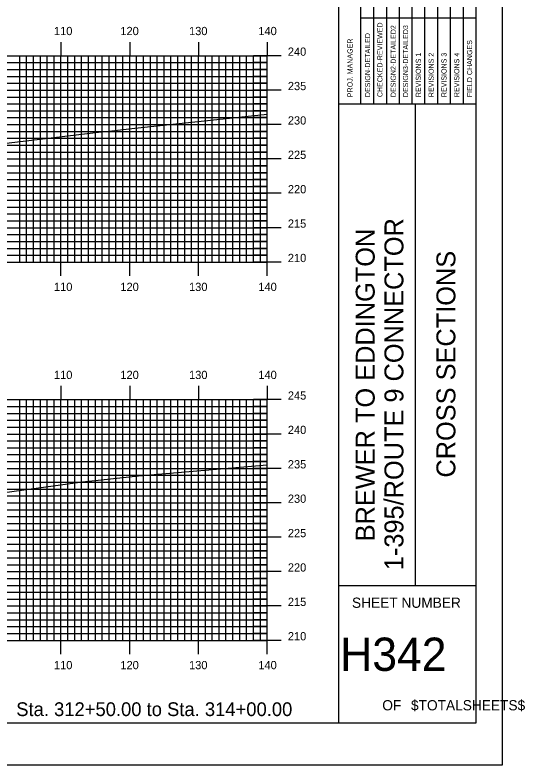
# Model space of a CAD drawing. Extents: x 1818850 to 1819194, y 442591 to 442811.
# Drawn here: x 1819119.5 to 1819193.6, y 442590.5 to 442699.6 of the extents above; entities that cross this region are included whole.
import ezdxf

# ---------------------------------------------------------------- set-up
doc = ezdxf.new("R2010")
doc.units = 0
for name, color, linetype in [('BORDER', 7, 'Continuous'), ('H_V ANNOTATION', 7, 'Continuous'), ('MAJOR', 7, 'Continuous'), ('MINOR', 7, 'Continuous'), ('PLOT BOUNDARY', 7, 'Continuous'), ('S_Roadway_Centerline', 7, 'Continuous')]:
    doc.layers.add(name, color=color, linetype=linetype)

msp = doc.modelspace()

# ---------------------------------------------------------------- linework, layer by layer
at = {"layer": 'BORDER'}
for p, q in [((1819166.55, 442596.67), (1819166.55, 442806.67)), ((1819166.55, 442686.67), (1819186.55, 442686.67)), ((1819177.73, 442616.67), (1819177.73, 442686.67)), ((1819166.55, 442616.67), (1819186.55, 442616.67))]:
    msp.add_line(p, q, dxfattribs=at)
msp.add_lwpolyline([(1818866.55, 442596.67), (1819186.55, 442596.67), (1819186.55, 442806.67), (1818866.55, 442806.67)], close=True, dxfattribs=at)
for points in [[(1819171.65, 442686.68), (1819171.65, 442721.67)], [(1819173.51, 442721.67), (1819173.51, 442686.68)], [(1819175.37, 442686.68), (1819175.37, 442721.67)], [(1819177.24, 442686.68), (1819177.24, 442721.67)], [(1819179.1, 442686.68), (1819179.1, 442721.67)], [(1819180.96, 442686.68), (1819180.96, 442721.67)], [(1819182.83, 442686.68), (1819182.83, 442721.67)], [(1819184.69, 442686.68), (1819184.69, 442721.67)], [(1819169.78, 442686.68), (1819169.78, 442720.26)], [(1819169.78, 442699.17), (1819186.55, 442699.17)]]:
    msp.add_lwpolyline(points, dxfattribs=at)
at = {"layer": 'MAJOR'}
for p, q in [((1819126.15, 442695.67), (1819126.15, 442693.67)), ((1819136.15, 442695.67), (1819136.15, 442693.67)), ((1819146.15, 442695.67), (1819146.15, 442693.67)), ((1819156.15, 442695.67), (1819156.15, 442693.67)), ((1818876.15, 442693.67), (1819156.15, 442693.67)), ((1818876.15, 442693.67), (1819156.15, 442693.67)), ((1819126.15, 442663.67), (1819126.15, 442693.67)), ((1819136.15, 442663.67), (1819136.15, 442693.67)), ((1819146.15, 442663.67), (1819146.15, 442693.67)), ((1819158.16, 442693.67), (1819154.15, 442693.67)), ((1819156.15, 442663.67), (1819156.15, 442693.67)), ((1819156.15, 442663.67), (1819156.15, 442693.67)), ((1818876.15, 442688.67), (1819156.15, 442688.67)), ((1819158.16, 442688.67), (1819154.15, 442688.67)), ((1818876.15, 442683.67), (1819156.15, 442683.67)), ((1819158.16, 442683.67), (1819154.15, 442683.67)), ((1818876.15, 442678.67), (1819156.15, 442678.67)), ((1819158.16, 442678.67), (1819154.15, 442678.67)), ((1818876.15, 442673.67), (1819156.15, 442673.67)), ((1819158.16, 442673.67), (1819154.15, 442673.67)), ((1818876.15, 442668.67), (1819156.15, 442668.67)), ((1819158.16, 442668.67), (1819154.15, 442668.67)), ((1818876.15, 442663.67), (1819156.15, 442663.67)), ((1818876.15, 442663.67), (1819156.15, 442663.67)), ((1819126.15, 442661.66), (1819126.15, 442663.67)), ((1819136.15, 442661.66), (1819136.15, 442663.67)), ((1819146.15, 442661.66), (1819146.15, 442663.67)), ((1819158.16, 442663.67), (1819154.15, 442663.67)), ((1819156.15, 442661.66), (1819156.15, 442663.67)), ((1819126.15, 442645.67), (1819126.15, 442643.67)), ((1819136.15, 442645.67), (1819136.15, 442643.67)), ((1819146.15, 442645.67), (1819146.15, 442643.67)), ((1819156.15, 442645.67), (1819156.15, 442643.67)), ((1818876.15, 442643.67), (1819156.15, 442643.67)), ((1818876.15, 442643.67), (1819156.15, 442643.67)), ((1819126.15, 442608.67), (1819126.15, 442643.67)), ((1819136.15, 442608.67), (1819136.15, 442643.67)), ((1819146.15, 442608.67), (1819146.15, 442643.67)), ((1819158.16, 442643.67), (1819154.15, 442643.67)), ((1819156.15, 442608.67), (1819156.15, 442643.67)), ((1819156.15, 442608.67), (1819156.15, 442643.67)), ((1818876.15, 442638.67), (1819156.15, 442638.67)), ((1819158.16, 442638.67), (1819154.15, 442638.67)), ((1818876.15, 442633.67), (1819156.15, 442633.67)), ((1819158.16, 442633.67), (1819154.15, 442633.67)), ((1818876.15, 442628.67), (1819156.15, 442628.67)), ((1819158.16, 442628.67), (1819154.15, 442628.67)), ((1818876.15, 442623.67), (1819156.15, 442623.67)), ((1819158.16, 442623.67), (1819154.15, 442623.67)), ((1818876.15, 442618.67), (1819156.15, 442618.67)), ((1819158.16, 442618.67), (1819154.15, 442618.67)), ((1818876.15, 442613.67), (1819156.15, 442613.67)), ((1819158.16, 442613.67), (1819154.15, 442613.67)), ((1818876.15, 442608.67), (1819156.15, 442608.67)), ((1818876.15, 442608.67), (1819156.15, 442608.67)), ((1819126.15, 442606.66), (1819126.15, 442608.67)), ((1819136.15, 442606.66), (1819136.15, 442608.67)), ((1819146.15, 442606.66), (1819146.15, 442608.67)), ((1819158.16, 442608.67), (1819154.15, 442608.67)), ((1819156.15, 442606.66), (1819156.15, 442608.67))]:
    msp.add_line(p, q, dxfattribs=at)
at = {"layer": 'MINOR'}
for p, q in [((1819120.15, 442663.67), (1819120.15, 442693.67)), ((1819121.15, 442663.67), (1819121.15, 442693.67)), ((1819122.15, 442663.67), (1819122.15, 442693.67)), ((1819123.15, 442663.67), (1819123.15, 442693.67)), ((1819124.15, 442663.67), (1819124.15, 442693.67)), ((1819125.15, 442663.67), (1819125.15, 442693.67)), ((1819127.15, 442663.67), (1819127.15, 442693.67)), ((1819128.15, 442663.67), (1819128.15, 442693.67)), ((1819129.15, 442663.67), (1819129.15, 442693.67)), ((1819130.15, 442663.67), (1819130.15, 442693.67)), ((1819131.15, 442663.67), (1819131.15, 442693.67)), ((1819132.15, 442663.67), (1819132.15, 442693.67)), ((1819133.15, 442663.67), (1819133.15, 442693.67)), ((1819134.15, 442663.67), (1819134.15, 442693.67)), ((1819135.15, 442663.67), (1819135.15, 442693.67)), ((1819137.15, 442663.67), (1819137.15, 442693.67)), ((1819138.15, 442663.67), (1819138.15, 442693.67)), ((1819139.15, 442663.67), (1819139.15, 442693.67)), ((1819140.15, 442663.67), (1819140.15, 442693.67)), ((1819141.15, 442663.67), (1819141.15, 442693.67)), ((1819142.15, 442663.67), (1819142.15, 442693.67)), ((1819143.15, 442663.67), (1819143.15, 442693.67)), ((1819144.15, 442663.67), (1819144.15, 442693.67)), ((1819145.15, 442663.67), (1819145.15, 442693.67)), ((1819147.15, 442663.67), (1819147.15, 442693.67)), ((1819148.15, 442663.67), (1819148.15, 442693.67)), ((1819149.15, 442663.67), (1819149.15, 442693.67)), ((1819150.15, 442663.67), (1819150.15, 442693.67)), ((1819151.15, 442663.67), (1819151.15, 442693.67)), ((1819152.15, 442663.67), (1819152.15, 442693.67)), ((1819153.15, 442663.67), (1819153.15, 442693.67)), ((1819154.15, 442663.67), (1819154.15, 442693.67)), ((1819155.15, 442663.67), (1819155.15, 442693.67)), ((1818876.15, 442692.67), (1819156.15, 442692.67)), ((1818876.15, 442691.67), (1819156.15, 442691.67)), ((1819156.15, 442692.67), (1819154.15, 442692.67)), ((1819156.15, 442691.67), (1819154.15, 442691.67)), ((1818876.15, 442690.67), (1819156.15, 442690.67)), ((1819156.15, 442690.67), (1819154.15, 442690.67)), ((1818876.15, 442689.67), (1819156.15, 442689.67)), ((1819156.15, 442689.67), (1819154.15, 442689.67)), ((1818876.15, 442687.67), (1819156.15, 442687.67)), ((1819156.15, 442687.67), (1819154.15, 442687.67)), ((1818876.15, 442686.67), (1819156.15, 442686.67)), ((1819156.15, 442686.67), (1819154.15, 442686.67)), ((1818876.15, 442685.67), (1819156.15, 442685.67)), ((1819156.15, 442685.67), (1819154.15, 442685.67)), ((1818876.15, 442684.67), (1819156.15, 442684.67)), ((1819156.15, 442684.67), (1819154.15, 442684.67)), ((1818876.15, 442682.67), (1819156.15, 442682.67)), ((1819156.15, 442682.67), (1819154.15, 442682.67)), ((1818876.15, 442681.67), (1819156.15, 442681.67)), ((1819156.15, 442681.67), (1819154.15, 442681.67)), ((1818876.15, 442680.67), (1819156.15, 442680.67)), ((1818876.15, 442679.67), (1819156.15, 442679.67)), ((1819156.15, 442680.67), (1819154.15, 442680.67)), ((1819156.15, 442679.67), (1819154.15, 442679.67)), ((1818876.15, 442677.67), (1819156.15, 442677.67)), ((1819156.15, 442677.67), (1819154.15, 442677.67)), ((1818876.15, 442676.67), (1819156.15, 442676.67)), ((1819156.15, 442676.67), (1819154.15, 442676.67)), ((1818876.15, 442675.67), (1819156.15, 442675.67)), ((1819156.15, 442675.67), (1819154.15, 442675.67)), ((1818876.15, 442674.67), (1819156.15, 442674.67)), ((1819156.15, 442674.67), (1819154.15, 442674.67)), ((1818876.15, 442672.67), (1819156.15, 442672.67)), ((1819156.15, 442672.67), (1819154.15, 442672.67)), ((1818876.15, 442671.67), (1819156.15, 442671.67)), ((1819156.15, 442671.67), (1819154.15, 442671.67)), ((1818876.15, 442670.67), (1819156.15, 442670.67)), ((1819156.15, 442670.67), (1819154.15, 442670.67)), ((1818876.15, 442669.67), (1819156.15, 442669.67)), ((1819156.15, 442669.67), (1819154.15, 442669.67)), ((1818876.15, 442667.67), (1819156.15, 442667.67)), ((1819156.15, 442667.67), (1819154.15, 442667.67)), ((1818876.15, 442666.67), (1819156.15, 442666.67)), ((1819156.15, 442666.67), (1819154.15, 442666.67)), ((1818876.15, 442665.67), (1819156.15, 442665.67)), ((1819156.15, 442665.67), (1819154.15, 442665.67)), ((1818876.15, 442664.67), (1819156.15, 442664.67)), ((1819156.15, 442664.67), (1819154.15, 442664.67)), ((1819120.15, 442608.67), (1819120.15, 442643.67)), ((1819121.15, 442608.67), (1819121.15, 442643.67)), ((1819122.15, 442608.67), (1819122.15, 442643.67)), ((1819123.15, 442608.67), (1819123.15, 442643.67)), ((1819124.15, 442608.67), (1819124.15, 442643.67)), ((1819125.15, 442608.67), (1819125.15, 442643.67)), ((1819127.15, 442608.67), (1819127.15, 442643.67)), ((1819128.15, 442608.67), (1819128.15, 442643.67)), ((1819129.15, 442608.67), (1819129.15, 442643.67)), ((1819130.15, 442608.67), (1819130.15, 442643.67)), ((1819131.15, 442608.67), (1819131.15, 442643.67)), ((1819132.15, 442608.67), (1819132.15, 442643.67)), ((1819133.15, 442608.67), (1819133.15, 442643.67)), ((1819134.15, 442608.67), (1819134.15, 442643.67)), ((1819135.15, 442608.67), (1819135.15, 442643.67)), ((1819137.15, 442608.67), (1819137.15, 442643.67)), ((1819138.15, 442608.67), (1819138.15, 442643.67)), ((1819139.15, 442608.67), (1819139.15, 442643.67)), ((1819140.15, 442608.67), (1819140.15, 442643.67)), ((1819141.15, 442608.67), (1819141.15, 442643.67)), ((1819142.15, 442608.67), (1819142.15, 442643.67)), ((1819143.15, 442608.67), (1819143.15, 442643.67)), ((1819144.15, 442608.67), (1819144.15, 442643.67)), ((1819145.15, 442608.67), (1819145.15, 442643.67)), ((1819147.15, 442608.67), (1819147.15, 442643.67)), ((1819148.15, 442608.67), (1819148.15, 442643.67)), ((1819149.15, 442608.67), (1819149.15, 442643.67)), ((1819150.15, 442608.67), (1819150.15, 442643.67)), ((1819151.15, 442608.67), (1819151.15, 442643.67)), ((1819152.15, 442608.67), (1819152.15, 442643.67)), ((1819153.15, 442608.67), (1819153.15, 442643.67)), ((1819154.15, 442608.67), (1819154.15, 442643.67)), ((1819155.15, 442608.67), (1819155.15, 442643.67)), ((1818876.15, 442642.67), (1819156.15, 442642.67)), ((1819156.15, 442642.67), (1819154.15, 442642.67)), ((1818876.15, 442641.67), (1819156.15, 442641.67)), ((1819156.15, 442641.67), (1819154.15, 442641.67)), ((1818876.15, 442640.67), (1819156.15, 442640.67)), ((1819156.15, 442640.67), (1819154.15, 442640.67)), ((1818876.15, 442639.67), (1819156.15, 442639.67)), ((1819156.15, 442639.67), (1819154.15, 442639.67)), ((1818876.15, 442637.67), (1819156.15, 442637.67)), ((1819156.15, 442637.67), (1819154.15, 442637.67)), ((1818876.15, 442636.67), (1819156.15, 442636.67)), ((1819156.15, 442636.67), (1819154.15, 442636.67)), ((1818876.15, 442635.67), (1819156.15, 442635.67)), ((1819156.15, 442635.67), (1819154.15, 442635.67)), ((1818876.15, 442634.67), (1819156.15, 442634.67)), ((1819156.15, 442634.67), (1819154.15, 442634.67)), ((1818876.15, 442632.67), (1819156.15, 442632.67)), ((1819156.15, 442632.67), (1819154.15, 442632.67)), ((1818876.15, 442631.67), (1819156.15, 442631.67)), ((1818876.15, 442630.67), (1819156.15, 442630.67)), ((1819156.15, 442631.67), (1819154.15, 442631.67)), ((1819156.15, 442630.67), (1819154.15, 442630.67)), ((1818876.15, 442629.67), (1819156.15, 442629.67)), ((1819156.15, 442629.67), (1819154.15, 442629.67)), ((1818876.15, 442627.67), (1819156.15, 442627.67)), ((1819156.15, 442627.67), (1819154.15, 442627.67)), ((1818876.15, 442626.67), (1819156.15, 442626.67)), ((1819156.15, 442626.67), (1819154.15, 442626.67)), ((1818876.15, 442625.67), (1819156.15, 442625.67)), ((1819156.15, 442625.67), (1819154.15, 442625.67)), ((1818876.15, 442624.67), (1819156.15, 442624.67)), ((1819156.15, 442624.67), (1819154.15, 442624.67)), ((1818876.15, 442622.67), (1819156.15, 442622.67)), ((1819156.15, 442622.67), (1819154.15, 442622.67)), ((1818876.15, 442621.67), (1819156.15, 442621.67)), ((1819156.15, 442621.67), (1819154.15, 442621.67)), ((1818876.15, 442620.67), (1819156.15, 442620.67)), ((1819156.15, 442620.67), (1819154.15, 442620.67)), ((1818876.15, 442619.67), (1819156.15, 442619.67)), ((1819156.15, 442619.67), (1819154.15, 442619.67)), ((1818876.15, 442617.67), (1819156.15, 442617.67)), ((1819156.15, 442617.67), (1819154.15, 442617.67)), ((1818876.15, 442616.67), (1819156.15, 442616.67)), ((1819156.15, 442616.67), (1819154.15, 442616.67)), ((1818876.15, 442615.67), (1819156.15, 442615.67)), ((1819156.15, 442615.67), (1819154.15, 442615.67)), ((1818876.15, 442614.67), (1819156.15, 442614.67)), ((1819156.15, 442614.67), (1819154.15, 442614.67)), ((1818876.15, 442612.67), (1819156.15, 442612.67)), ((1819156.15, 442612.67), (1819154.15, 442612.67)), ((1818876.15, 442611.67), (1819156.15, 442611.67)), ((1819156.15, 442611.67), (1819154.15, 442611.67)), ((1818876.15, 442610.67), (1819156.15, 442610.67)), ((1819156.15, 442610.67), (1819154.15, 442610.67)), ((1818876.15, 442609.67), (1819156.15, 442609.67)), ((1819156.15, 442609.67), (1819154.15, 442609.67))]:
    msp.add_line(p, q, dxfattribs=at)
at = {"layer": 'PLOT BOUNDARY'}
msp.add_lwpolyline([(1818850.36, 442590.55), (1819190.36, 442590.55), (1819190.36, 442810.55), (1818850.36, 442810.55)], close=True, dxfattribs=at)
at = {"layer": 'S_Roadway_Centerline'}
for points in [[(1819070.78, 442675.98), (1819083.88, 442677.52), (1819088.1, 442677.88), (1819108.17, 442679.61), (1819116.53, 442680.76), (1819131.59, 442682.54), (1819132.8, 442682.68), (1819133.55, 442682.76), (1819136.43, 442683.09), (1819156.15, 442685.18)], [(1819064.07, 442624.48), (1819079.13, 442626.05), (1819088.35, 442627.04), (1819105.32, 442628.54), (1819112.2, 442629.38), (1819126.08, 442631.29), (1819129.29, 442631.7), (1819137.42, 442632.57), (1819156.15, 442634.19)]]:
    msp.add_lwpolyline(points, dxfattribs=at)

# ---------------------------------------------------------------- texts
at = {"layer": 'BORDER'}
for s, height, p in [('CHECKED-REVIEWED', 0.7455, (1819172.91, 442687.65)), ('DESIGN2-DETAILED2', 0.7455, (1819174.85, 442687.65)), ('DESIGN3-DETAILED3', 0.7455, (1819176.64, 442687.65)), ('DESIGN-DETAILED', 0.7455, (1819171.12, 442687.65)), ('PROJ. MANAGER', 0.7455, (1819168.56, 442687.65)), ('FIELD CHANGES', 0.7455, (1819185.96, 442687.65)), ('REVISIONS 1', 0.7455, (1819178.5, 442687.65)), ('REVISIONS 2', 0.7455, (1819180.37, 442687.65)), ('REVISIONS 3', 0.7455, (1819182.23, 442687.65)), ('REVISIONS 4', 0.7455, (1819184.09, 442687.65)), ('1-395/ROUTE 9 CONNECTOR', 2.7557, (1819175.96, 442618.87)), ('BREWER TO EDDINGTON', 2.7557, (1819171.78, 442623.07)), ('CROSS SECTIONS', 2.7557, (1819183.52, 442632.34))]:
    msp.add_text(s, height=height, rotation=90, dxfattribs=at).set_placement(p)
for s, height, p in [('SHEET NUMBER', 1.4905, (1819168.48, 442613.4)), ('H342', 4.839, (1819166.76, 442604.23)), ('$TOTALSHEETS$', 1.4905, (1819177.06, 442598.49)), ('OF', 1.491, (1819172.89, 442598.49))]:
    msp.add_text(s, height=height, dxfattribs=at).set_placement(p)
at = {"layer": 'H_V ANNOTATION'}
for s, height, p in [('110', 1.2, (1819125.13, 442696.67)), ('120', 1.2, (1819134.79, 442696.67)), ('130', 1.2, (1819144.78, 442696.67)), ('140', 1.2, (1819154.86, 442696.67)), ('240', 1.2, (1819159.15, 442693.67)), ('235', 1.2, (1819159.15, 442688.67)), ('230', 1.2, (1819159.15, 442683.67)), ('225', 1.2, (1819159.15, 442678.67)), ('220', 1.2, (1819159.15, 442673.67)), ('215', 1.2, (1819159.15, 442668.67)), ('210', 1.2, (1819159.15, 442663.67)), ('110', 1.2, (1819125.13, 442659.47)), ('120', 1.2, (1819134.79, 442659.47)), ('130', 1.2, (1819144.78, 442659.47)), ('140', 1.2, (1819154.86, 442659.47)), ('110', 1.2, (1819125.13, 442646.67)), ('120', 1.2, (1819134.79, 442646.67)), ('130', 1.2, (1819144.78, 442646.67)), ('140', 1.2, (1819154.86, 442646.67)), ('245', 1.2, (1819159.15, 442643.67)), ('240', 1.2, (1819159.15, 442638.67)), ('235', 1.2, (1819159.15, 442633.67)), ('230', 1.2, (1819159.15, 442628.67)), ('225', 1.2, (1819159.15, 442623.67)), ('220', 1.2, (1819159.15, 442618.67)), ('215', 1.2, (1819159.15, 442613.67)), ('210', 1.2, (1819159.15, 442608.67)), ('110', 1.2, (1819125.13, 442604.47)), ('120', 1.2, (1819134.79, 442604.47)), ('130', 1.2, (1819144.78, 442604.47)), ('140', 1.2, (1819154.86, 442604.47)), ('Sta. 312+50.00 to Sta. 314+00.00', 2.0004, (1819119.64, 442597.66))]:
    msp.add_text(s, height=height, dxfattribs=at).set_placement(p)

doc.saveas('drawing.dxf')
